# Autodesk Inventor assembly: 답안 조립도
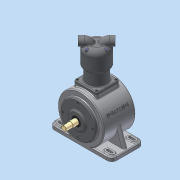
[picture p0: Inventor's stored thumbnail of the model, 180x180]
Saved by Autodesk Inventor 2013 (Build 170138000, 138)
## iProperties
Created: 2015-06
Part Number: 답안 조립도
Document SubType Name: Assembly
Designer: Administrator
Author: Administrator
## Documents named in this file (15)
- C:\Users\Administrator\Desktop\450606V1035\답안 조립도.iam
- C:\Users\Administrator\Desktop\450606V1035\M4x0.7.ipt
- C:\Users\Administrator\Desktop\450606V1035\M5x0.8.ipt
- C:\Users\Administrator\Desktop\450606V1035\답안 본체.ipt
- C:\Users\Administrator\Desktop\450606V1035\메인 크랭크 축-구동부.ipt
- C:\Users\Administrator\Desktop\450606V1035\메인커버.ipt
- C:\Users\Administrator\Desktop\450606V1035\베어링 6204.ipt
- C:\Users\Administrator\Desktop\450606V1035\베어링 NA 4902.ipt
- C:\Users\Administrator\Desktop\450606V1035\실린더.ipt
- C:\Users\Administrator\Desktop\450606V1035\실린더헤드.ipt
- C:\Users\Administrator\Desktop\450606V1035\오일실.ipt
- C:\Users\Administrator\Desktop\450606V1035\커넥팅 로드.ipt
- C:\Users\Administrator\Desktop\450606V1035\크랭크 서브축.ipt
- C:\Users\Administrator\Desktop\450606V1035\피스톤 핀.ipt
- C:\Users\Administrator\Desktop\450606V1035\피스톤.ipt
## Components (14 placed, 4 different names)
1. 피스톤 핀:1
2. 피스톤:1
3. M4x0.7:2
4. M4x0.7:3
5. M4x0.7:4
6. M4x0.7:5
7. M4x0.7:6
8. M4x0.7:7
9. M4x0.7:8
10. M4x0.7:9
11. M5x0.8:1
12. M5x0.8:2
13. M5x0.8:3
14. M5x0.8:4
